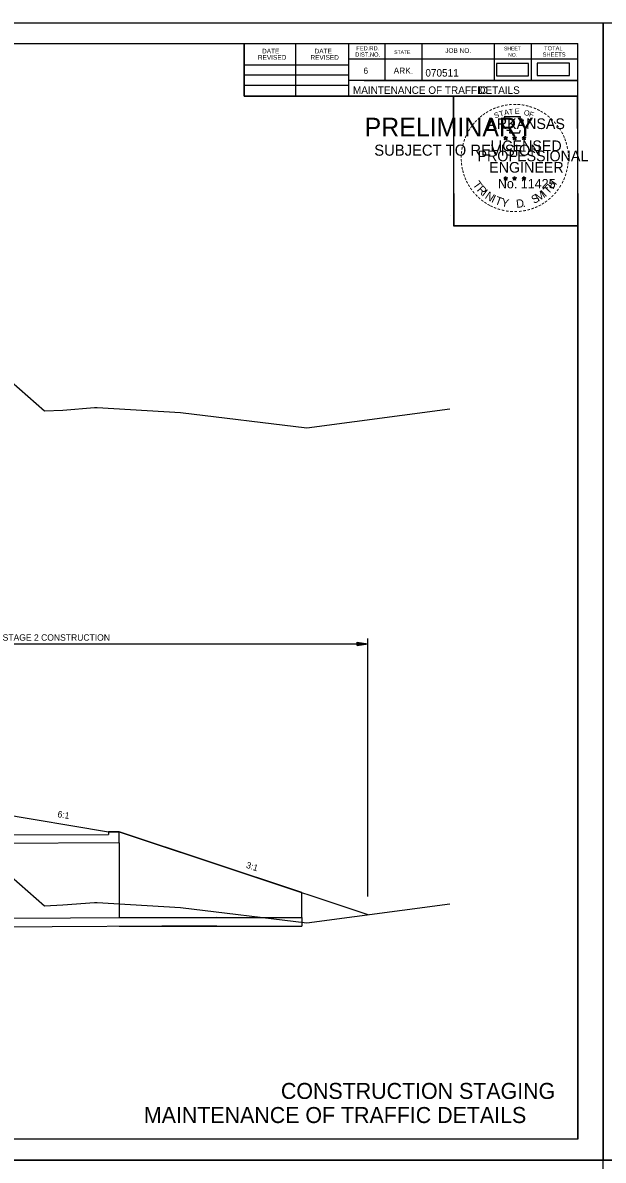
# Model space of a CAD drawing. Extents: x 1398460 to 1408037, y 380768 to 383968.
# Drawn here: x 1400121 to 1400666, y 382901 to 383968 of the extents above; entities that cross this region are included whole.
import ezdxf

# ---------------------------------------------------------------- set-up
doc = ezdxf.new("R2010")
doc.units = 0
for name, color, linetype in [('R_Border', 7, 'Continuous'), ('R_Border PE', 7, 'Continuous'), ('R_Border Prem', 7, 'Continuous'), ('R_Dimension', 7, 'Continuous'), ('R_Draft', 7, 'Continuous'), ('R_Exist Surface', 7, 'Continuous'), ('R_Fin Surface', 7, 'Continuous'), ('R_No Plot', 7, 'Continuous'), ('R_Water', 7, 'Continuous')]:
    doc.layers.add(name, color=color, linetype=linetype)

msp = doc.modelspace()

# ---------------------------------------------------------------- linework, layer by layer
at = {"layer": 'R_Border'}
for p, q in [((1399060.9, 383948.1), (1400641.8, 383948.1)), ((1400328.6, 383898.7), (1400328.6, 383948.1)), ((1400377, 383898.7), (1400377, 383948.1)), ((1400426.3, 383948.1), (1400426.3, 383898.7)), ((1400460.5, 383948.1), (1400460.5, 383913.4)), ((1400495.2, 383948.1), (1400495.2, 383913.4)), ((1400563.1, 383948.1), (1400563.1, 383913.4)), ((1400597.8, 383948.1), (1400597.8, 383913.4)), ((1400641.8, 382920.8), (1400641.8, 383948.1)), ((1400641.8, 383933.4), (1400426.3, 383933.4)), ((1400641.8, 383933.5), (1400641.8, 383933.5)), ((1400328.6, 383928), (1400426.3, 383928)), ((1400328.6, 383918.7), (1400426.3, 383918.7)), ((1400641.8, 383913.4), (1400426.3, 383913.4)), ((1400441.1, 383913.4), (1400641.8, 383913.4)), ((1400328.6, 383909), (1400426.3, 383909)), ((1400641.8, 383898.7), (1400328.6, 383898.7)), ((1400641.8, 382920.8), (1399060.9, 382920.8))]:
    msp.add_line(p, q, dxfattribs=at)
at = {"layer": 'R_Border PE'}
for p, q in [((1400572.2, 383860), (1400573.9, 383859.4)), ((1400572.2, 383860), (1400573.5, 383859.8)), ((1400572.2, 383860), (1400573.4, 383859.4)), ((1400572.9, 383857.9), (1400573.9, 383859.4)), ((1400572.9, 383857.9), (1400573.5, 383859.2)), ((1400572.9, 383857.9), (1400573.9, 383859)), ((1400573.9, 383861.3), (1400573.7, 383860)), ((1400573.9, 383859.4), (1400573.9, 383861.3)), ((1400573.9, 383861.3), (1400574.2, 383860)), ((1400575.7, 383860), (1400573.9, 383859.4)), ((1400575, 383857.9), (1400573.9, 383859.4)), ((1400575, 383857.9), (1400573.9, 383859)), ((1400575.7, 383860), (1400574.2, 383859.7)), ((1400575, 383857.9), (1400574.3, 383859.4)), ((1400575.7, 383860), (1400574.7, 383859.5)), ((1400580.5, 383860), (1400582.3, 383859.4)), ((1400580.5, 383860), (1400581.8, 383859.8)), ((1400580.5, 383860), (1400581.7, 383859.4)), ((1400581.2, 383857.9), (1400582.3, 383859.4)), ((1400581.2, 383857.9), (1400581.8, 383859.2)), ((1400581.2, 383857.9), (1400582.3, 383859)), ((1400582.3, 383861.3), (1400582.1, 383860)), ((1400582.3, 383859.4), (1400582.3, 383861.3)), ((1400582.3, 383861.3), (1400582.5, 383860)), ((1400584, 383860), (1400582.3, 383859.4)), ((1400583.4, 383857.9), (1400582.3, 383859.4)), ((1400583.4, 383857.9), (1400582.3, 383859)), ((1400584, 383860), (1400582.6, 383859.7)), ((1400583.4, 383857.9), (1400582.7, 383859.4)), ((1400584, 383860), (1400583, 383859.5)), ((1400589.4, 383859.9), (1400591.1, 383859.4)), ((1400589.4, 383859.9), (1400590.6, 383859.7)), ((1400589.4, 383859.9), (1400590.5, 383859.3)), ((1400590, 383857.9), (1400591.1, 383859.4)), ((1400590, 383857.9), (1400590.7, 383859.1)), ((1400590, 383857.9), (1400591.1, 383859)), ((1400591.1, 383861.2), (1400590.9, 383859.9)), ((1400591.1, 383859.4), (1400591.1, 383861.2)), ((1400591.1, 383861.2), (1400591.4, 383859.9)), ((1400592.8, 383859.9), (1400591.1, 383859.4)), ((1400592.2, 383857.9), (1400591.1, 383859.4)), ((1400592.2, 383857.9), (1400591.1, 383859)), ((1400592.8, 383859.9), (1400591.4, 383859.7)), ((1400592.2, 383857.9), (1400591.5, 383859.3)), ((1400592.8, 383859.9), (1400591.8, 383859.4)), ((1400572.2, 383822.1), (1400573.9, 383821.6)), ((1400572.2, 383822.1), (1400573.4, 383821.9)), ((1400572.2, 383822.1), (1400573.4, 383821.5)), ((1400572.8, 383820.1), (1400573.9, 383821.6)), ((1400572.8, 383820.1), (1400573.5, 383821.3)), ((1400572.8, 383820.1), (1400573.9, 383821.2)), ((1400573.9, 383823.4), (1400573.7, 383822.1)), ((1400573.9, 383821.6), (1400573.9, 383823.4)), ((1400573.9, 383823.4), (1400574.2, 383822.1)), ((1400575.7, 383822.1), (1400573.9, 383821.6)), ((1400575, 383820.1), (1400573.9, 383821.6)), ((1400575, 383820.1), (1400573.9, 383821.1)), ((1400575.7, 383822.1), (1400574.2, 383821.9)), ((1400575, 383820.1), (1400574.3, 383821.5)), ((1400575.7, 383822.1), (1400574.6, 383821.6)), ((1400580.5, 383822.1), (1400582.3, 383821.6)), ((1400580.5, 383822.1), (1400581.8, 383821.9)), ((1400580.5, 383822.1), (1400581.7, 383821.5)), ((1400581.2, 383820.1), (1400582.3, 383821.6)), ((1400581.2, 383820.1), (1400581.8, 383821.3)), ((1400581.2, 383820.1), (1400582.3, 383821.2)), ((1400582.3, 383823.4), (1400582.1, 383822.1)), ((1400582.3, 383821.6), (1400582.3, 383823.4)), ((1400582.3, 383823.4), (1400582.5, 383822.1)), ((1400584, 383822.1), (1400582.3, 383821.6)), ((1400583.3, 383820.1), (1400582.3, 383821.6)), ((1400583.3, 383820.1), (1400582.3, 383821.1)), ((1400584, 383822.1), (1400582.6, 383821.9)), ((1400583.3, 383820.1), (1400582.6, 383821.5)), ((1400584, 383822.1), (1400583, 383821.6)), ((1400589.4, 383822.1), (1400591.1, 383821.5)), ((1400589.4, 383822.1), (1400590.6, 383821.8)), ((1400589.4, 383822.1), (1400590.5, 383821.5)), ((1400590, 383820), (1400591.1, 383821.5)), ((1400590, 383820), (1400590.6, 383821.2)), ((1400590, 383820), (1400591.1, 383821.1)), ((1400591.1, 383823.3), (1400590.9, 383822.1)), ((1400591.1, 383821.5), (1400591.1, 383823.3)), ((1400591.1, 383823.3), (1400591.3, 383822.1)), ((1400592.8, 383822.1), (1400591.1, 383821.5)), ((1400592.2, 383820), (1400591.1, 383821.5)), ((1400592.2, 383820), (1400591.1, 383821.1)), ((1400592.8, 383822.1), (1400591.4, 383821.8)), ((1400592.2, 383820), (1400591.5, 383821.5)), ((1400592.8, 383822.1), (1400591.8, 383821.6))]:
    msp.add_line(p, q, dxfattribs=at)
for points in [[(1400572.4, 383879.4), (1400573.7, 383875.2)], [(1400590, 383874.8), (1400590.7, 383876.2), (1400587.2, 383876.1), (1400588, 383879.4), (1400572.4, 383879.4)], [(1400573.9, 383861.3), (1400575, 383857.9), (1400572.2, 383860), (1400575.7, 383860), (1400572.9, 383857.9), (1400573.9, 383861.3)], [(1400574.9, 383867.3), (1400574.9, 383866.8), (1400577.7, 383866.7), (1400577.4, 383864.4), (1400586.8, 383864.4), (1400587.8, 383867)], [(1400582.3, 383861.3), (1400583.4, 383857.9), (1400580.5, 383860), (1400584, 383860), (1400581.2, 383857.9), (1400582.3, 383861.3)], [(1400591.1, 383861.2), (1400592.2, 383857.9), (1400589.4, 383859.9), (1400592.8, 383859.9), (1400590, 383857.9), (1400591.1, 383861.2)], [(1400573.9, 383823.4), (1400575, 383820.1), (1400572.2, 383822.1), (1400575.7, 383822.1), (1400572.8, 383820.1), (1400573.9, 383823.4)], [(1400582.3, 383823.4), (1400583.3, 383820.1), (1400580.5, 383822.1), (1400584, 383822.1), (1400581.2, 383820.1), (1400582.3, 383823.4)], [(1400591.1, 383823.3), (1400592.2, 383820), (1400589.4, 383822.1), (1400592.8, 383822.1), (1400590, 383820), (1400591.1, 383823.3)]]:
    msp.add_lwpolyline(points, dxfattribs=at)
for centre, radius in [((1400573.9, 383859.4), 0.861), ((1400573.9, 383859.4), 0.723), ((1400573.9, 383859.4), 0.579), ((1400573.9, 383859.4), 0.495), ((1400573.9, 383859.4), 0.374), ((1400573.9, 383859.4), 0.248), ((1400573.9, 383859.4), 0.148), ((1400582.3, 383859.4), 0.861), ((1400582.3, 383859.4), 0.723), ((1400582.3, 383859.4), 0.579), ((1400582.3, 383859.4), 0.495), ((1400582.3, 383859.4), 0.374), ((1400582.3, 383859.4), 0.248), ((1400582.3, 383859.4), 0.148), ((1400591.1, 383859.4), 0.861), ((1400591.1, 383859.4), 0.723), ((1400591.1, 383859.4), 0.579), ((1400591.1, 383859.4), 0.495), ((1400591.1, 383859.4), 0.374), ((1400591.1, 383859.4), 0.248), ((1400591.1, 383859.4), 0.148), ((1400573.9, 383821.6), 0.861), ((1400573.9, 383821.6), 0.723), ((1400573.9, 383821.6), 0.579), ((1400573.9, 383821.6), 0.495), ((1400573.9, 383821.6), 0.374), ((1400573.9, 383821.6), 0.248), ((1400573.9, 383821.6), 0.148), ((1400582.3, 383821.6), 0.861), ((1400582.3, 383821.6), 0.723), ((1400582.3, 383821.6), 0.579), ((1400582.3, 383821.6), 0.495), ((1400582.3, 383821.6), 0.374), ((1400582.3, 383821.6), 0.248), ((1400582.3, 383821.6), 0.148), ((1400591.1, 383821.5), 0.861), ((1400591.1, 383821.5), 0.723), ((1400591.1, 383821.5), 0.579), ((1400591.1, 383821.5), 0.495), ((1400591.1, 383821.5), 0.374), ((1400591.1, 383821.5), 0.248), ((1400591.1, 383821.5), 0.148)]:
    msp.add_circle(centre, radius, dxfattribs=at)
at = {"layer": 'R_Dimension'}
for p, q in [((1400444.7, 383148.1), (1400444.7, 383390.1)), ((1399866.7, 383385.1), (1400444.7, 383385.1)), ((1400434.7, 383386.6), (1400444.7, 383385.1)), ((1400434.7, 383383.6), (1400434.7, 383386.6)), ((1400434.7, 383386.4), (1400443.1, 383385.1)), ((1400434.7, 383386.1), (1400441.4, 383385.1)), ((1400434.7, 383385.9), (1400439.7, 383385.1)), ((1400434.7, 383385.6), (1400438, 383385.1)), ((1400434.7, 383385.4), (1400436.3, 383385.1)), ((1400434.7, 383383.6), (1400444.7, 383385.1)), ((1400434.7, 383384.6), (1400438, 383385.1)), ((1400434.7, 383384.1), (1400441.4, 383385.1)), ((1400434.7, 383383.9), (1400443.1, 383385.1)), ((1400434.7, 383384.4), (1400439.7, 383385.1)), ((1400434.7, 383384.9), (1400436.3, 383385.1))]:
    msp.add_line(p, q, dxfattribs=at)
for points in [[(1400565.2, 383917.7), (1400595.5, 383917.7), (1400595.5, 383929.3), (1400565.2, 383929.3)], [(1400603.5, 383918.2), (1400633.8, 383918.2), (1400633.8, 383929.8), (1400603.5, 383929.8)]]:
    msp.add_lwpolyline(points, close=True, dxfattribs=at)
at = {"layer": 'R_Exist Surface'}
for points in [[(1400054.8, 383679.2), (1400141.2, 383603.6), (1400158.4, 383604.3), (1400187.9, 383606.7), (1400190.4, 383606.7), (1400268.8, 383602.1), (1400387.2, 383587.6), (1400521.6, 383605.5)], [(1400054.8, 383215.1), (1400141.2, 383139.5), (1400158.4, 383140.3), (1400187.9, 383142.6), (1400190.4, 383142.7), (1400268.8, 383138), (1400387.2, 383123.6), (1400521.6, 383141.5)]]:
    msp.add_lwpolyline(points, dxfattribs=at)
at = {"layer": 'R_Fin Surface'}
msp.add_line((1400046.7, 383234.8), (1400201.3, 383209), dxfattribs=at)
msp.add_lwpolyline([(1400201.3, 383209), (1400211.3, 383209), (1400444.7, 383131.2)], dxfattribs=at)
at = {"layer": 'R_No Plot'}
for p, q in [((1398998.9, 383967.6), (1400665.5, 383967.6)), ((1400521.9, 383786.4), (1400521.9, 383786.4)), ((1398998.9, 382900.9), (1400665.5, 382900.9))]:
    msp.add_line(p, q, dxfattribs=at)
for points in [[(1398998.8, 383967.6), (1400665.5, 383967.6), (1400665.5, 382900.9), (1398998.8, 382900.9)], [(1400665.5, 383967.6), (1402332.2, 383967.6), (1402332.2, 382900.9), (1400665.5, 382900.9)], [(1400230.5, 383948.1), (1400328.6, 383948.1), (1400328.6, 383898.7), (1400409.1, 383898.7), (1400525.1, 383898.7), (1400525.1, 383777), (1400641.8, 383777), (1400641.8, 382920.8), (1399060.9, 382920.8), (1399060.9, 383948.1)], [(1400525.1, 383898.7), (1400641.2, 383898.7), (1400641.8, 383777), (1400525.7, 383777)], [(1400665.5, 382900.9), (1402332.2, 382900.9), (1402332.2, 381834.2), (1400665.5, 381834.2)]]:
    msp.add_lwpolyline(points, close=True, dxfattribs=at)
at = {"layer": 'R_Water'}
for p, q in [((1400382.7, 383151.9), (1400211.3, 383209)), ((1399866.7, 383204.8), (1400201.3, 383206.4)), ((1400211.3, 383198.5), (1399866.7, 383196.9)), ((1400211.3, 383198.6), (1400211.3, 383128.6)), ((1400382.7, 383128.6), (1400382.7, 383151.9)), ((1399866.7, 383126.9), (1400302.5, 383128.9)), ((1400211.3, 383128.6), (1400382.7, 383128.6)), ((1400382.7, 383128.6), (1400382.7, 383120.3)), ((1400302.5, 383120.6), (1399866.7, 383118.5)), ((1400211.3, 383120.3), (1400382.7, 383120.3))]:
    msp.add_line(p, q, dxfattribs=at)
msp.add_lwpolyline([(1400211.3, 383198.6), (1400211.3, 383209), (1400201.3, 383209), (1400201.3, 383206.5)], dxfattribs=at)

# ---------------------------------------------------------------- texts
at = {"layer": 'R_Border'}
for s, height, p in [('FED.RD.', 3.91, (1400433.7, 383941.7)), ('JOB NO.', 4.4, (1400517.2, 383939.3)), ('SHEET', 3.42, (1400572.4, 383941.7)), ('TOTAL', 3.91, (1400610, 383941.7)), ('REVISED', 4.4, (1400341.4, 383932.9)), ('DATE', 4.4, (1400345.3, 383938.8)), ('REVISED', 4.4, (1400390.7, 383932.9)), ('DATE', 4.4, (1400394.6, 383938.8)), ('DIST.NO.', 3.91, (1400432.7, 383935.8)), ('STATE', 3.42, (1400469.3, 383938.3)), ('NO.', 3.42, (1400576.3, 383935.8)), ('SHEETS', 3.91, (1400608.6, 383935.8)), ('6', 5.86, (1400440.5, 383919.7)), ('ARK.', 5.86, (1400468.8, 383919.7)), ('070511', 7, (1400498.6, 383917.1)), ('MAINTENANCE OF TRAFFIC', 7, (1400430.6, 383900.9)), (' DETAILS', 7, (1400545.6, 383900.9)), ('CONSTRUCTION STAGING', 15, (1400363, 382958.4)), ('MAINTENANCE OF TRAFFIC DETAILS', 15, (1400234.4, 382935.8))]:
    msp.add_text(s, height=height, dxfattribs=at).set_placement(p)
at = {"layer": 'R_Border PE'}
for s, height, rotation, p in [('-', 8, 13.6302, (1400569.9, 383886.2)), ('-', 8, 10.2193, (1400573.3, 383887)), ('-', 8, 5.8968, (1400576.9, 383887.6)), ('-', 8, 0.1862, (1400580.8, 383887.9)), ('-', 8, 357.743, (1400584.4, 383887.9)), ('-', 8, 352.1617, (1400588.1, 383887.6)), ('-', 8, 347.2049, (1400591.7, 383887)), ('-', 8, 38.9507, (1400551.5, 383876.4)), ('-', 8, 36.2317, (1400553.9, 383878.3)), ('-', 8, 34.0636, (1400556.8, 383880.2)), ('-', 8, 28.7918, (1400559.8, 383882.1)), ('-', 8, 24.3072, (1400563, 383883.7)), ('S', 5, 21.594, (1400564.2, 383877.8)), ('-', 8, 19.1761, (1400566.1, 383885)), ('T', 5, 16.4036, (1400568.7, 383879.4)), ('A', 5, 11.2132, (1400572.9, 383880.7)), ('T', 5, 6.0228, (1400577.1, 383881.5)), ('E', 5, 0.8323, (1400582.6, 383882.1)), ('O', 5, 350.4515, (1400590.7, 383881)), ('F', 5, 340.0707, (1400595.4, 383879.9)), ('-', 8, 342.3362, (1400594.9, 383886.2)), ('-', 8, 337.8551, (1400598.6, 383885.1)), ('-', 8, 334.1211, (1400601.7, 383883.8)), ('-', 8, 329.6409, (1400604.6, 383882.4)), ('-', 8, 325.8627, (1400607.8, 383880.6)), ('-', 8, 320.5297, (1400610.9, 383878.4)), ('-', 8, 54.2325, (1400543.1, 383866.6)), ('-', 8, 50.6142, (1400545.1, 383869.5)), ('-', 8, 48.4231, (1400547.1, 383871.9)), ('-', 8, 42.9622, (1400549.4, 383874.3)), ('-', 8, 315.5786, (1400613.9, 383876)), ('-', 8, 309.8797, (1400616.7, 383873.2)), ('-', 8, 306.6522, (1400619.3, 383870.2)), ('-', 8, 72.3945, (1400537.5, 383854.7)), ('-', 8, 67.7743, (1400538.6, 383857.9)), ('-', 8, 62.8713, (1400539.9, 383860.9)), ('-', 8, 58.0706, (1400541.4, 383864)), ('-', 7, 303.6753, (1400621.8, 383867.4)), ('-', 8, 299.6684, (1400623.4, 383864.3)), ('-', 8, 294.6628, (1400625, 383861.3)), ('-', 8, 290.5728, (1400626.3, 383858.4)), ('-', 8, 81.2013, (1400535.8, 383847.6)), ('-', 8, 75.461, (1400536.5, 383851.1)), ('-', 8, 285.1233, (1400627.4, 383855.5)), ('-', 8, 280.5493, (1400628.4, 383851.8)), ('-', 8, 276.5962, (1400629.3, 383848)), ('-', 8, 94.1959, (1400535.5, 383837)), ('-', 8, 89.0622, (1400535.3, 383840.6)), ('-', 8, 85.1863, (1400535.5, 383844.1)), ('-', 8, 263.5172, (1400629.6, 383837.9)), ('-', 8, 274.3301, (1400629.6, 383844.3)), ('-', 8, 269.9407, (1400629.7, 383841.2)), ('-', 8, 98.9479, (1400535.9, 383833.7)), ('-', 8, 101.7149, (1400536.5, 383830)), ('-', 8, 105.4578, (1400537.4, 383827)), ('-', 8, 252.8681, (1400627.8, 383827.6)), ('-', 8, 255.7626, (1400628.7, 383831.2)), ('-', 8, 260.9953, (1400629.3, 383834.6)), ('-', 8, 109.0874, (1400538.4, 383823.9)), ('-', 8, 114.0643, (1400539.7, 383820.9)), ('-', 8, 115.7289, (1400541.2, 383817.8)), ('-', 8, 120.4471, (1400543, 383814.9)), ('T', 7.7, 306.0406, (1400542.7, 383815.8)), ('T', 7.7, 46.6444, (1400613.9, 383806.2)), ('H', 7.7, 54.6088, (1400618.3, 383810.9)), ('-', 8, 244.6197, (1400625.4, 383821.1)), ('-', 8, 247.8887, (1400626.7, 383824.2)), ('-', 8, 125.8934, (1400545, 383812.1)), ('-', 8, 130.7181, (1400547.3, 383809.3)), ('-', 8, 134.2238, (1400549.9, 383806.6)), ('R', 7.7, 314.005, (1400546.5, 383810.5)), ('I', 7.7, 321.9694, (1400551, 383805.9)), ('N', 7.7, 326.5002, (1400553.9, 383803.5)), ('I', 7.7, 335.3603, (1400559.9, 383799.6)), ('T', 7.7, 339.8912, (1400563.2, 383797.9)), ('S', 7.7, 26.9312, (1400600.4, 383797.6)), ('M', 7.7, 32.6563, (1400604.6, 383799.6)), ('I', 7.7, 42.1136, (1400611.1, 383803.8)), ('-', 8, 225.7653, (1400616.9, 383808.4)), ('-', 8, 231.2538, (1400619.3, 383811.2)), ('-', 8, 233.8452, (1400621.4, 383814.1)), ('-', 8, 239.0712, (1400623.4, 383817.3)), ('-', 8, 138.9338, (1400552.5, 383804.3)), ('-', 8, 144.6463, (1400555.3, 383802.2)), ('-', 8, 148.0898, (1400558.1, 383800.4)), ('-', 8, 151.5704, (1400561, 383798.7)), ('-', 8, 154.6002, (1400563.6, 383797.5)), ('-', 8, 158.5612, (1400566.8, 383796.2)), ('Y', 7.7, 347.8556, (1400569.3, 383795.7)), ('D', 7.7, 6.3969, (1400584.2, 383793.9)), ('.', 7.7, 13.7642, (1400590.2, 383794.5)), ('-', 8, 204.2516, (1400602.9, 383798.2)), ('-', 8, 207.3568, (1400606.1, 383799.8)), ('-', 8, 212.2491, (1400608.8, 383801.6)), ('-', 8, 215.7363, (1400611.5, 383803.5)), ('-', 8, 221.0851, (1400614.3, 383805.9)), ('-', 8, 162.7983, (1400570.2, 383795.2)), ('-', 8, 167.5555, (1400573.8, 383794.4)), ('-', 8, 173.1155, (1400577.6, 383793.8)), ('-', 8, 176.5183, (1400581.4, 383793.5)), ('-', 8, 181.5918, (1400585.1, 383793.6)), ('-', 8, 185.8167, (1400589.1, 383794)), ('-', 8, 191.2858, (1400592.8, 383794.7)), ('-', 8, 195.4743, (1400596.5, 383795.7)), ('-', 8, 200.7184, (1400599.8, 383796.9))]:
    msp.add_text(s, height=height, rotation=rotation, dxfattribs=at).set_placement(p)
for s, height, p in [('ARKANSAS', 10, (1400556.7, 383867.9)), ('DWB', 0.05, (1400573.9, 383859.4)), ('DWB', 0.05, (1400582.2, 383859.4)), ('DWB', 0.05, (1400591, 383859.3)), ('PROFESSIONAL', 10, (1400547.5, 383837.7)), ('LICENSED', 10, (1400559.6, 383847.2)), ('ENGINEER', 10, (1400558.5, 383827)), ('No. 11425', 8.78, (1400566.6, 383812.3)), ('DWB', 0.05, (1400573.9, 383821.5)), ('DWB', 0.05, (1400582.2, 383821.5)), ('DWB', 0.05, (1400591, 383821.5))]:
    msp.add_text(s, height=height, dxfattribs=at).set_placement(p)
at = {"layer": 'R_Border Prem'}
for s, height, p in [('PRELIMINARY', 17.5, (1400441.5, 383861)), ('DWB', 0.05, (1400445.3, 383870.3)), ('SUBJECT TO REVISION', 10.376, (1400450.6, 383842.9))]:
    msp.add_text(s, height=height, dxfattribs=at).set_placement(p)
at = {"layer": 'R_Dimension'}
msp.add_text('STAGE 2 CONSTRUCTION', height=6, dxfattribs=at).set_placement((1400101.8, 383388.1))
at = {"layer": 'R_Draft'}
for s, rotation, p in [('6:1', 350.5377, (1400153, 383222.7)), ('3:1', 341.5652, (1400329.8, 383175.3))]:
    msp.add_text(s, height=6, rotation=rotation, dxfattribs=at).set_placement(p)

doc.saveas('drawing.dxf')
